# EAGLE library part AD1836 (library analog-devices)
Multichannel 96 kHz Codec Auto generated by make-symbol-device-package-bsdl.ulp Rev. 32 Source: http://www.analog.com/static/imported-files/data_sheets/AD1836.pdf
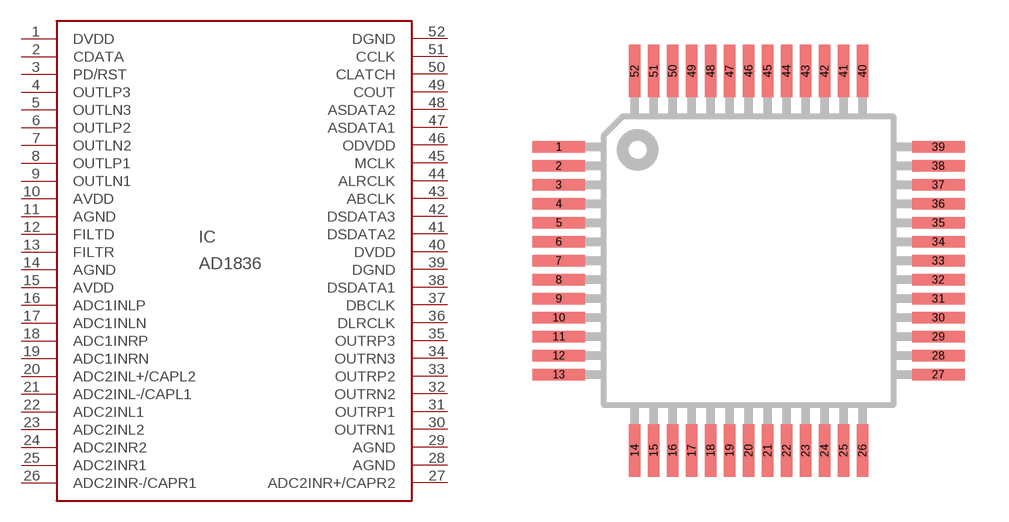
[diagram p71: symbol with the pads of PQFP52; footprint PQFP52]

Designator prefix IC

## AD1836 (MF: ALTERA CORPORATION; MPN: AD1836AASZ; OC_FARNELL: 8396558; OC_NEWARK: 59K3418)  [PQFP52]
1  DVDD  pwr
2  CDATA  in
3  PD/RST  in
4  OUTLP3  out
5  OUTLN3  out
6  OUTLP2  out
7  OUTLN2  out
8  OUTLP1  out
9  OUTLN1  out
10  AVDD  in
11  AGND  in
12  FILTD  in
13  FILTR  in
14  AGND  in
15  AVDD  in
16  ADC1INLP  in
17  ADC1INLN  in
18  ADC1INRP  in
19  ADC1INRN  in
20  ADC2INL+/CAPL2  in
21  ADC2INL-/CAPL1  in
22  ADC2INL1  in
23  ADC2INL2  in
24  ADC2INR2  in
25  ADC2INR1  in
26  ADC2INR-/CAPR1  in
27  ADC2INR+/CAPR2  in
28  AGND  in
29  AGND  in
30  OUTRN1  out
31  OUTRP1  out
32  OUTRN2  out
33  OUTRP2  out
34  OUTRN3  out
35  OUTRP3  out
36  DLRCLK
37  DBCLK
38  DSDATA1  in
39  DGND  pwr
40  DVDD  pwr
41  DSDATA2  in
42  DSDATA3  in
43  ABCLK  out
44  ALRCLK  out
45  MCLK  in
46  ODVDD  in
47  ASDATA1  out
48  ASDATA2  out
49  COUT  out
50  CLATCH  in
51  CCLK  in
52  DGND  pwr

## Footprint PQFP52 (pad centres in mm)
PLASTIC QUAD FLAT PACK
smd 1.8 x 0.4: 1 -6.5,3.9; 2 -6.5,3.25; 3 -6.5,2.6; 4 -6.5,1.95; 5 -6.5,1.3; 6 -6.5,0.65; 7 -6.5,0; 8 -6.5,-0.65; 9 -6.5,-1.3; 10 -6.5,-1.95; 11 -6.5,-2.6; 12 -6.5,-3.25; 13 -6.5,-3.9; 27 6.5,-3.9; 28 6.5,-3.25; 29 6.5,-2.6; 30 6.5,-1.95; 31 6.5,-1.3; 32 6.5,-0.65; 33 6.5,0; 34 6.5,0.65; 35 6.5,1.3; 36 6.5,1.95; 37 6.5,2.6; 38 6.5,3.25; 39 6.5,3.9
smd 0.4 x 1.8: 14 -3.9,-6.5; 15 -3.25,-6.5; 16 -2.6,-6.5; 17 -1.95,-6.5; 18 -1.3,-6.5; 19 -0.65,-6.5; 20 0,-6.5; 21 0.65,-6.5; 22 1.3,-6.5; 23 1.95,-6.5; 24 2.6,-6.5; 25 3.25,-6.5; 26 3.9,-6.5; 40 3.9,6.5; 41 3.25,6.5; 42 2.6,6.5; 43 1.95,6.5; 44 1.3,6.5; 45 0.65,6.5; 46 0,6.5; 47 -0.65,6.5; 48 -1.3,6.5; 49 -1.95,6.5; 50 -2.6,6.5; 51 -3.25,6.5; 52 -3.9,6.5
